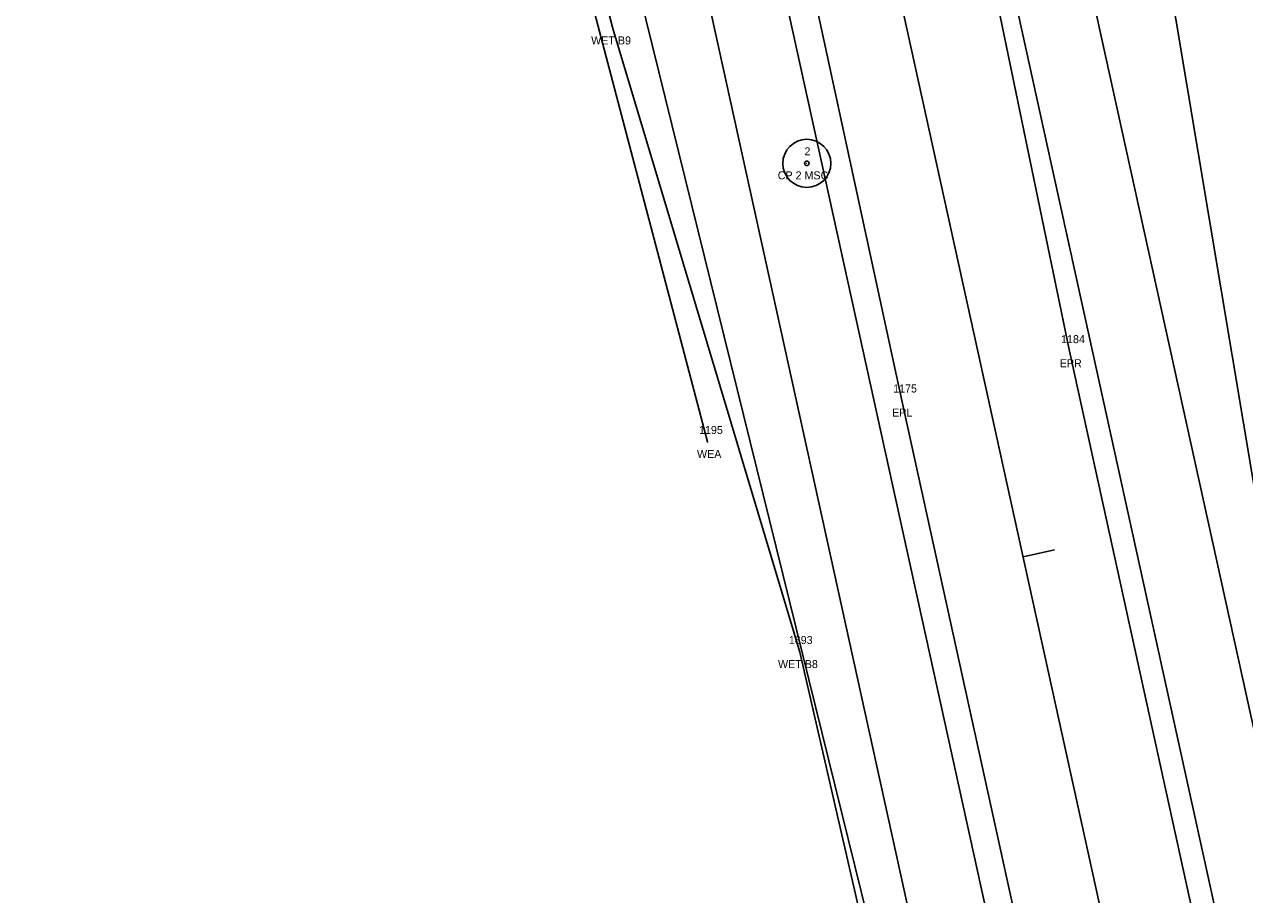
# Model space of a CAD drawing. Extents: x 2521558 to 2524785, y 882711 to 887632.
# Drawn here: x 2523707.4 to 2523859.8, y 884884.6 to 884993.3 of the extents above; entities that cross this region are included whole.
import ezdxf

# ---------------------------------------------------------------- set-up
doc = ezdxf.new("R2010")
doc.units = 0
for name, color, linetype in [('RD_EV_JurisArea', 7, 'Continuous'), ('RD_EX_H2O', 7, 'Continuous'), ('RD_EX_H2O_txCode', 7, 'Continuous'), ('RD_EX_H2O_WetLd_txCode', 7, 'Continuous'), ('RD_EX_Road', 7, 'Continuous'), ('RD_EX_Road_txCode', 7, 'Continuous'), ('RD_EX_VEG', 7, 'Continuous'), ('RD_HC_Cl', 7, 'Continuous'), ('RD_HC_Data', 7, 'Continuous'), ('RD_HC_Data_Tic', 7, 'Continuous'), ('RD_HC_txCode', 7, 'Continuous'), ('RD_PD_Final_TrvlWay', 7, 'Continuous'), ('RD_PD_GR', 7, 'Continuous'), ('RD_PD_SuperShp1', 7, 'Continuous'), ('RD_SMD_Locator', 7, 'Continuous')]:
    doc.layers.add(name, color=color, linetype=linetype)

msp = doc.modelspace()

# ---------------------------------------------------------------- linework, layer by layer
at = {"layer": 'RD_EV_JurisArea'}
for points in [[(2523944.86, 884550.08), (2523910.41, 884709.58), (2523888.01, 884815.03), (2523863.93, 884918.37), (2523848.43, 885010.84), (2523837.07, 885095.13), (2523817.82, 885104.47)], [(2523827.75, 884469.64), (2523867.43, 884517.67), (2523885.95, 884534.84), (2523882.77, 884582.72), (2523847.74, 884736.42), (2523822.93, 884833.79), (2523804.26, 884914.89), (2523780.91, 884992.76), (2523770.73, 885031.48), (2523760.5, 885068.9)]]:
    msp.add_lwpolyline(points, dxfattribs=at)
at = {"layer": 'RD_EX_H2O'}
msp.add_lwpolyline([(2523792.73, 884941.12), (2523763.67, 885051.56), (2523756.26, 885062.72), (2523770.47, 885094.55), (2523817.57, 885105.71), (2523827.83, 885106)], dxfattribs=at)
at = {"layer": 'RD_EX_Road'}
for p, q in [((2523837.97, 884952.46), (2523817.58, 885050.92)), ((2523817, 884946.3), (2523795.47, 885045.91)), ((2523858.56, 884858.71), (2523837.97, 884952.46)), ((2523837.34, 884853.78), (2523817, 884946.3))]:
    msp.add_line(p, q, dxfattribs=at)
at = {"layer": 'RD_EX_VEG'}
msp.add_lwpolyline([(2523800.23, 884418.22), (2523892.24, 884498.97), (2523844.57, 884752.81), (2523771.94, 885046.88), (2523769.06, 885076.62)], dxfattribs=at)
at = {"layer": 'RD_HC_Cl'}
msp.add_line((2523641.17, 885794.2), (2524197.76, 883266.56), dxfattribs=at)
at = {"layer": 'RD_HC_Data'}
for radius in [3, 0.282]:
    msp.add_circle((2523805.14, 884975.91), radius, dxfattribs=at)
at = {"layer": 'RD_HC_Data_Tic'}
msp.add_line((2523832.17, 884926.78), (2523836.08, 884927.64), dxfattribs=at)
at = {"layer": 'RD_PD_Final_TrvlWay'}
for p, q in [((2523724.34, 885481.57), (2524039.39, 884050.85)), ((2523697, 885475.55), (2524012.05, 884044.83))]:
    msp.add_line(p, q, dxfattribs=at)
at = {"layer": 'RD_PD_GR'}
for p, q in [((2523833.35, 885030.72), (2523900.02, 884727.97)), ((2523854.12, 884717.86), (2523787.45, 885020.61))]:
    msp.add_line(p, q, dxfattribs=at)
at = {"layer": 'RD_PD_SuperShp1'}
for p, q in [((2524039.39, 884050.85), (2523724.34, 885481.57)), ((2524025.72, 884047.84), (2523710.67, 885478.56)), ((2523710.67, 885478.56), (2524025.72, 884047.84)), ((2523697, 885475.55), (2524012.05, 884044.83))]:
    msp.add_line(p, q, dxfattribs=at)
at = {"layer": 'RD_SMD_Locator'}
for centre in [(2523780.91, 884992.76), (2523805.14, 884975.91), (2523837.97, 884952.46), (2523817, 884946.3), (2523792.73, 884941.12), (2523804.26, 884914.89)]:
    msp.add_circle(centre, 0.001, dxfattribs=at)

# ---------------------------------------------------------------- texts
at = {"layer": 'RD_EX_H2O_txCode'}
for s, p in [('1195', (2523791.67, 884942.12)), ('WEA', (2523791.42, 884939.12))]:
    msp.add_text(s, height=1, dxfattribs=at).set_placement(p)
at = {"layer": 'RD_EX_H2O_WetLd_txCode'}
for s, p in [('WET B9', (2523778.19, 884990.76)), ('1693', (2523802.89, 884915.89)), ('WET B8', (2523801.54, 884912.89))]:
    msp.add_text(s, height=1, dxfattribs=at).set_placement(p)
at = {"layer": 'RD_EX_Road_txCode'}
for s, p in [('1184', (2523836.91, 884953.46)), ('EPR', (2523836.74, 884950.46)), ('1175', (2523815.93, 884947.3)), ('EPL', (2523815.79, 884944.3))]:
    msp.add_text(s, height=1, dxfattribs=at).set_placement(p)
at = {"layer": 'RD_HC_txCode'}
for s, p in [('2', (2523804.85, 884976.91)), ('CP 2 MSC', (2523801.51, 884973.91))]:
    msp.add_text(s, height=1, dxfattribs=at).set_placement(p)

doc.saveas('drawing.dxf')
